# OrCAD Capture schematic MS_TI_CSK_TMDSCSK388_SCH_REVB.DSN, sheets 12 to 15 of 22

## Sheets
12 12.WLAN TRANSLATORS & CAM MUXER: size C; title: WLAN TRANSLATORS & CAM MUXER
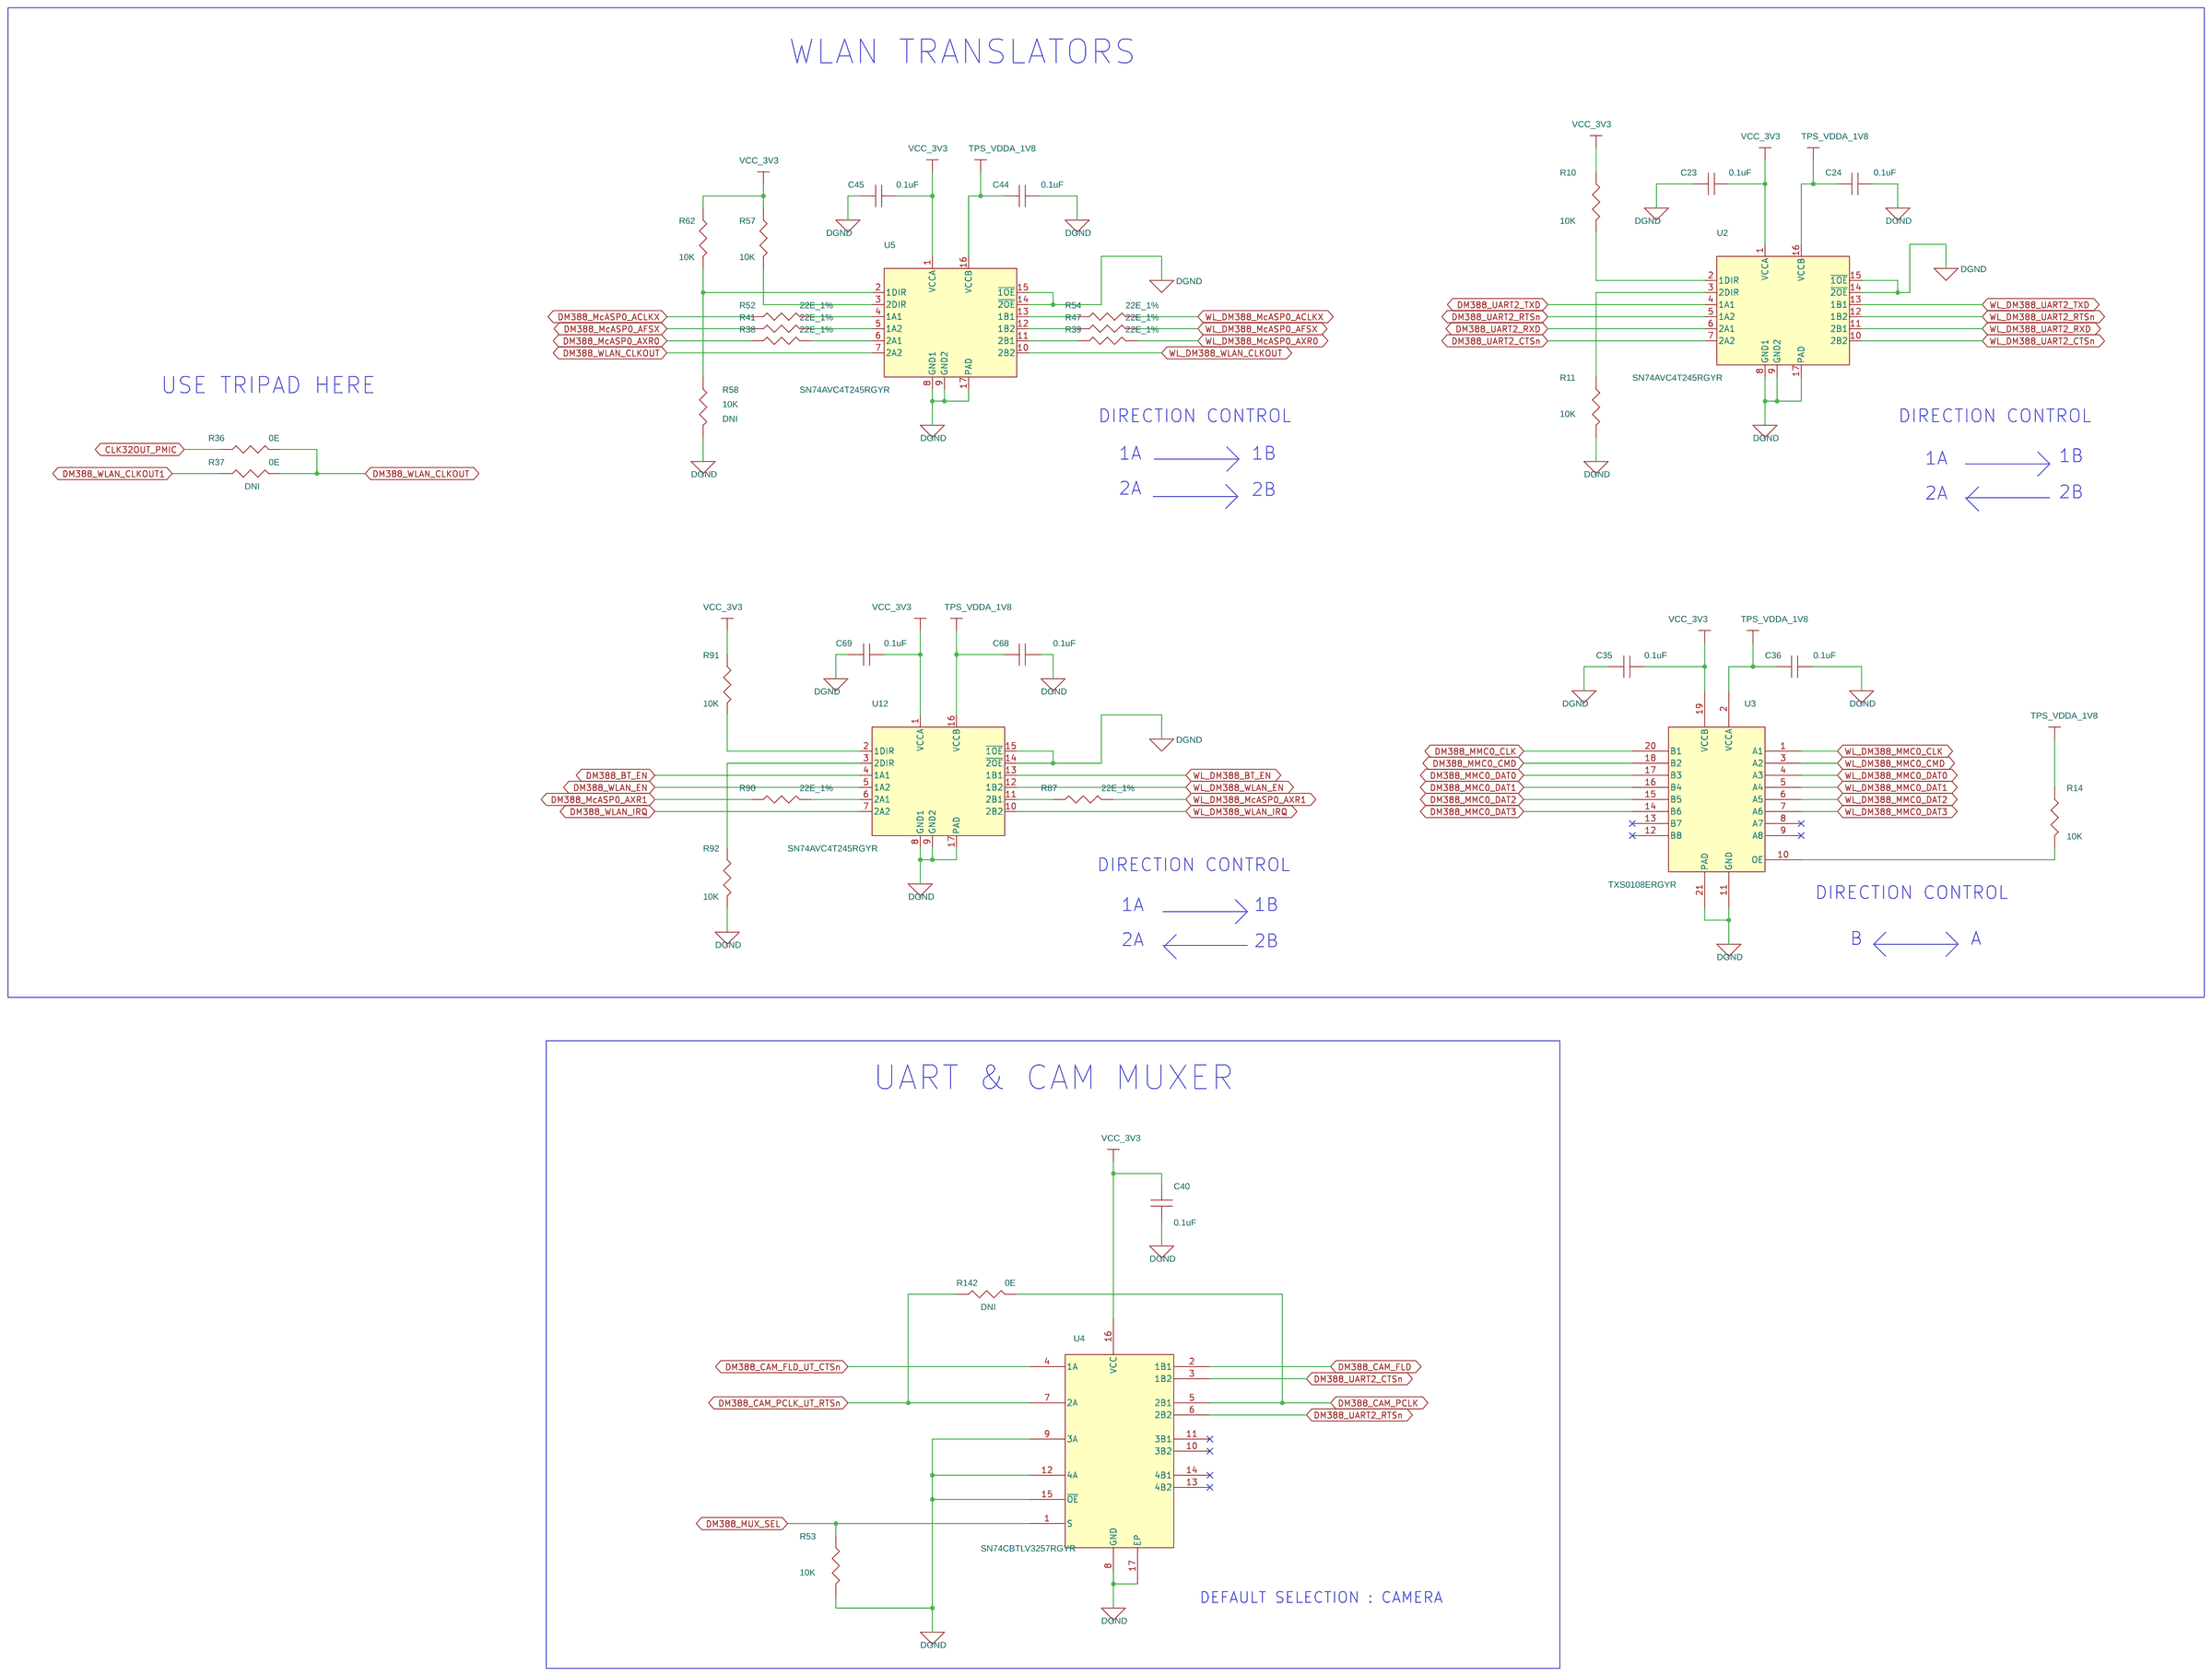
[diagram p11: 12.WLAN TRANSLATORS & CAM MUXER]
13 13.WLAN + BT MODULE: size C; title: WLAN + BT MODULE
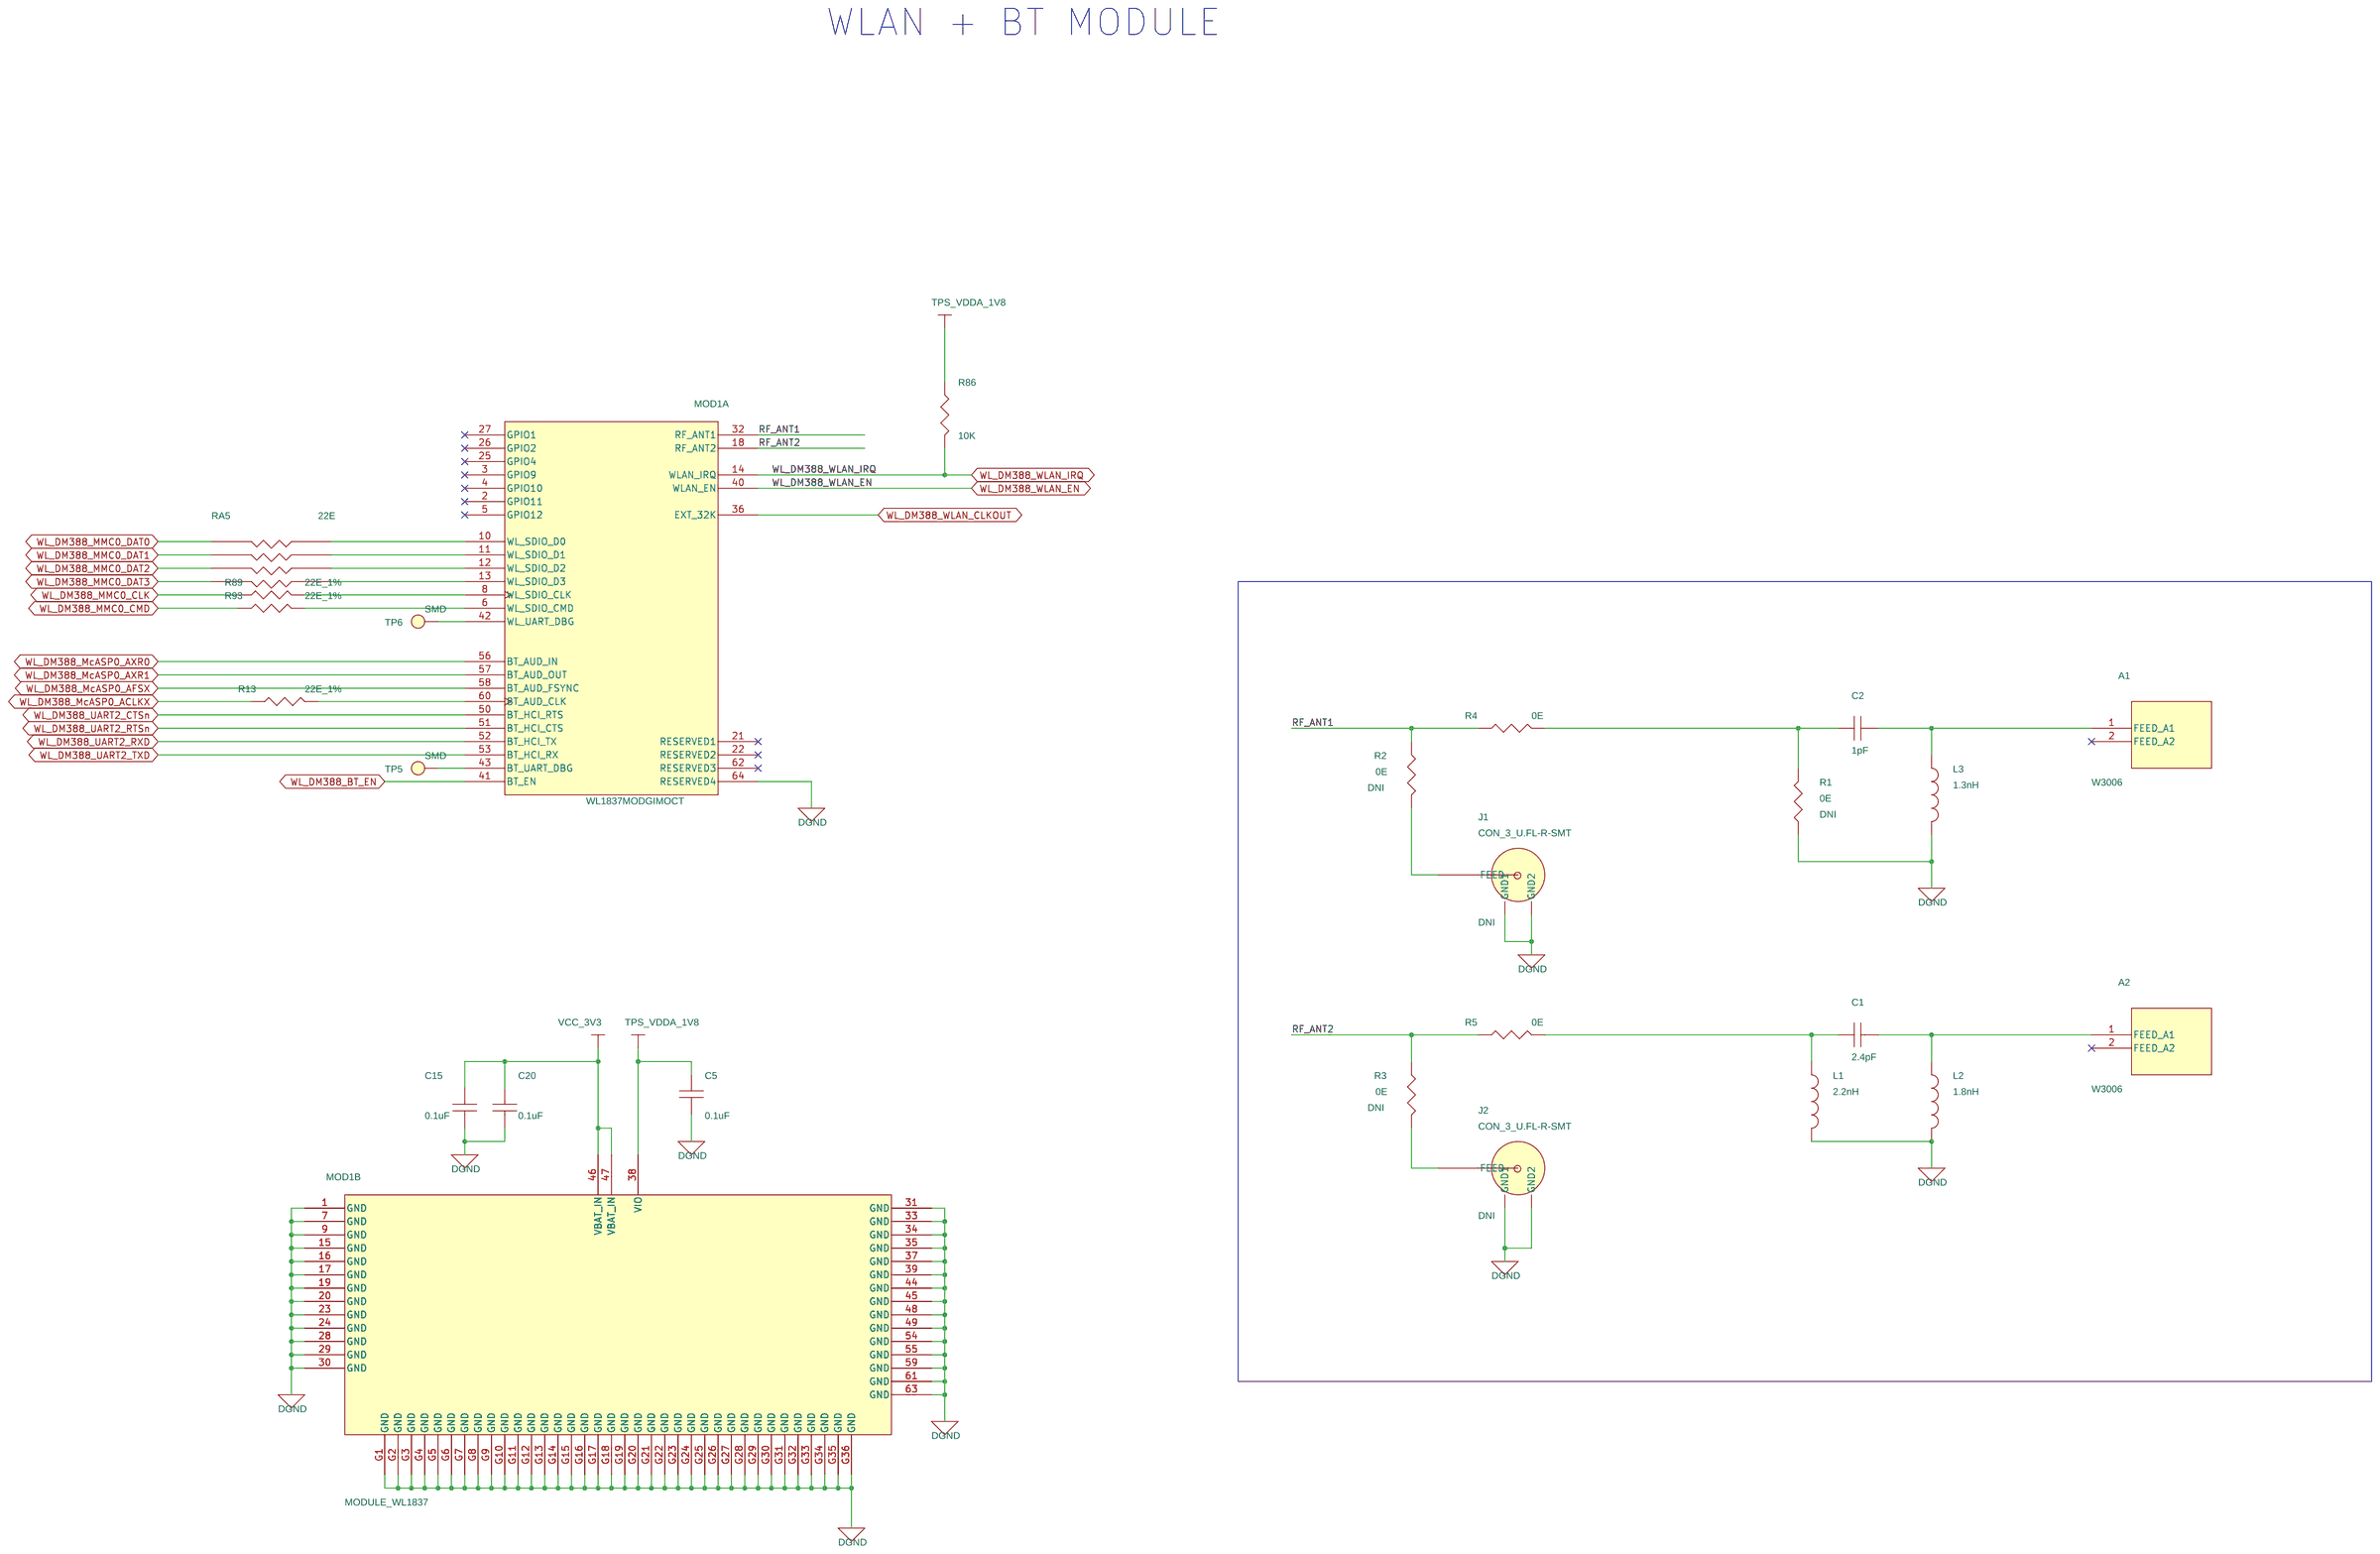
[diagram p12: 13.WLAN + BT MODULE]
14 14.DM388 POWER: size C; title: DM388 POWER
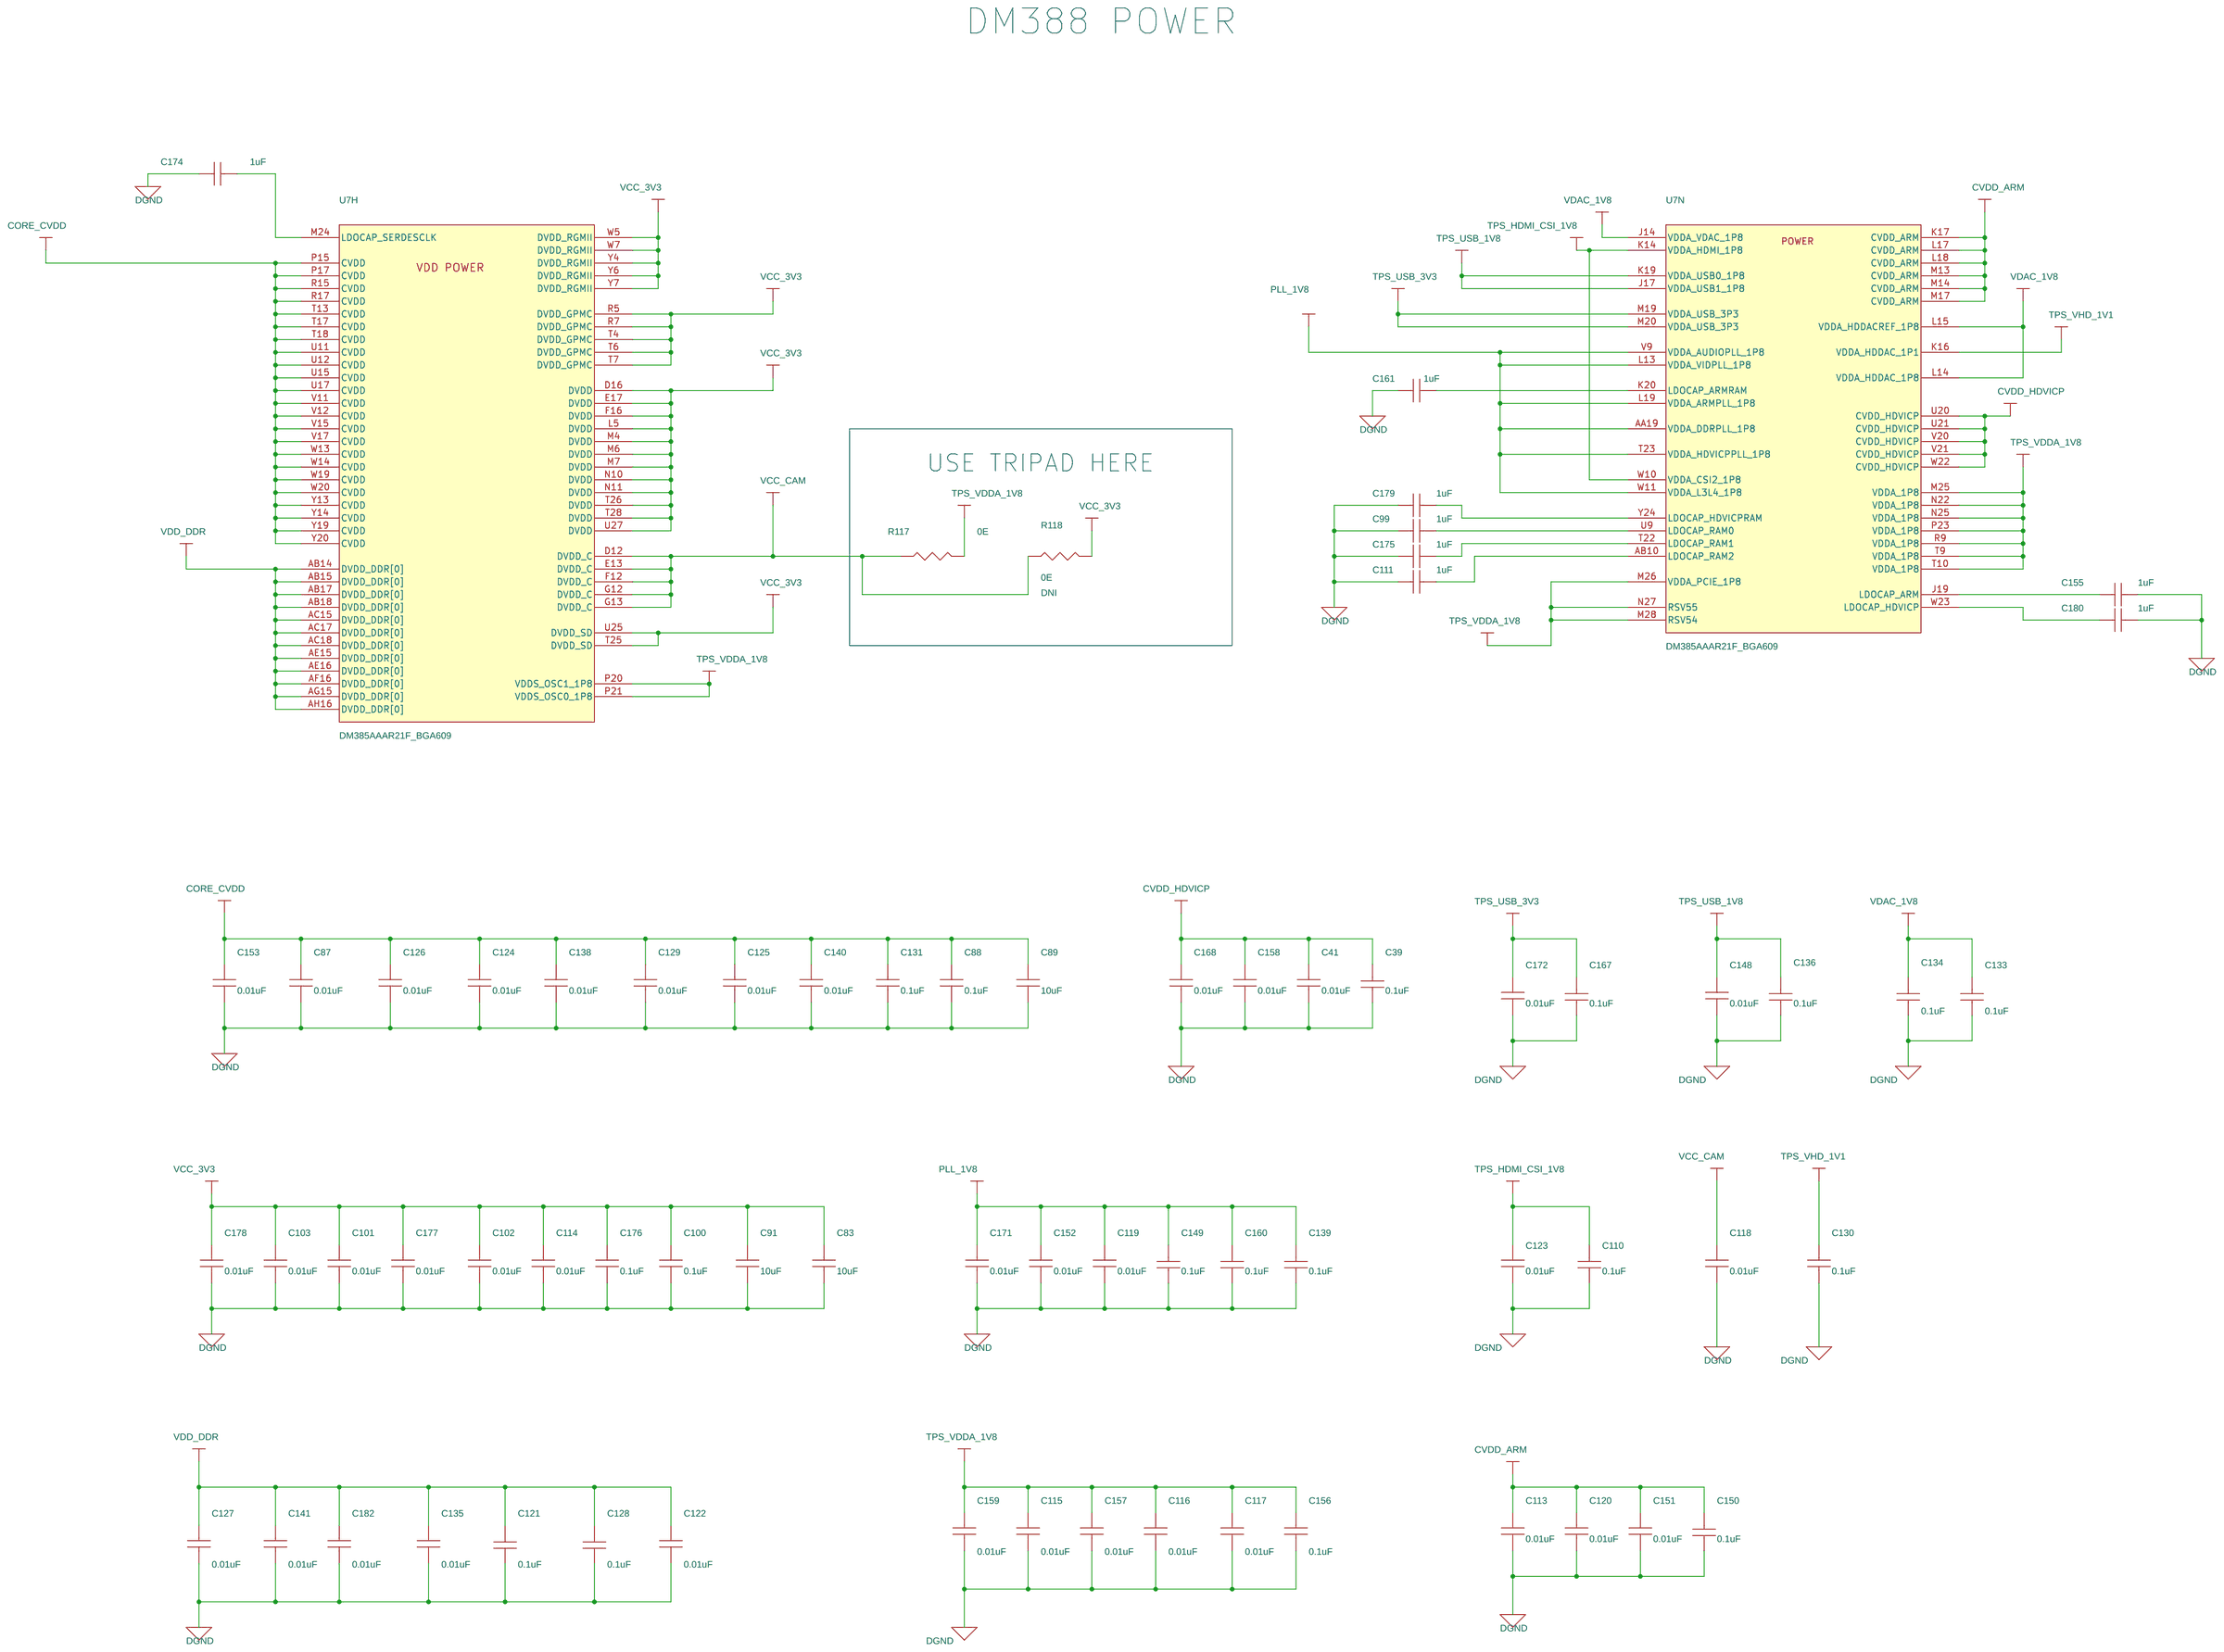
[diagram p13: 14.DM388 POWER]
15 15.DM388 VSS: size C; title: DM388 VSS
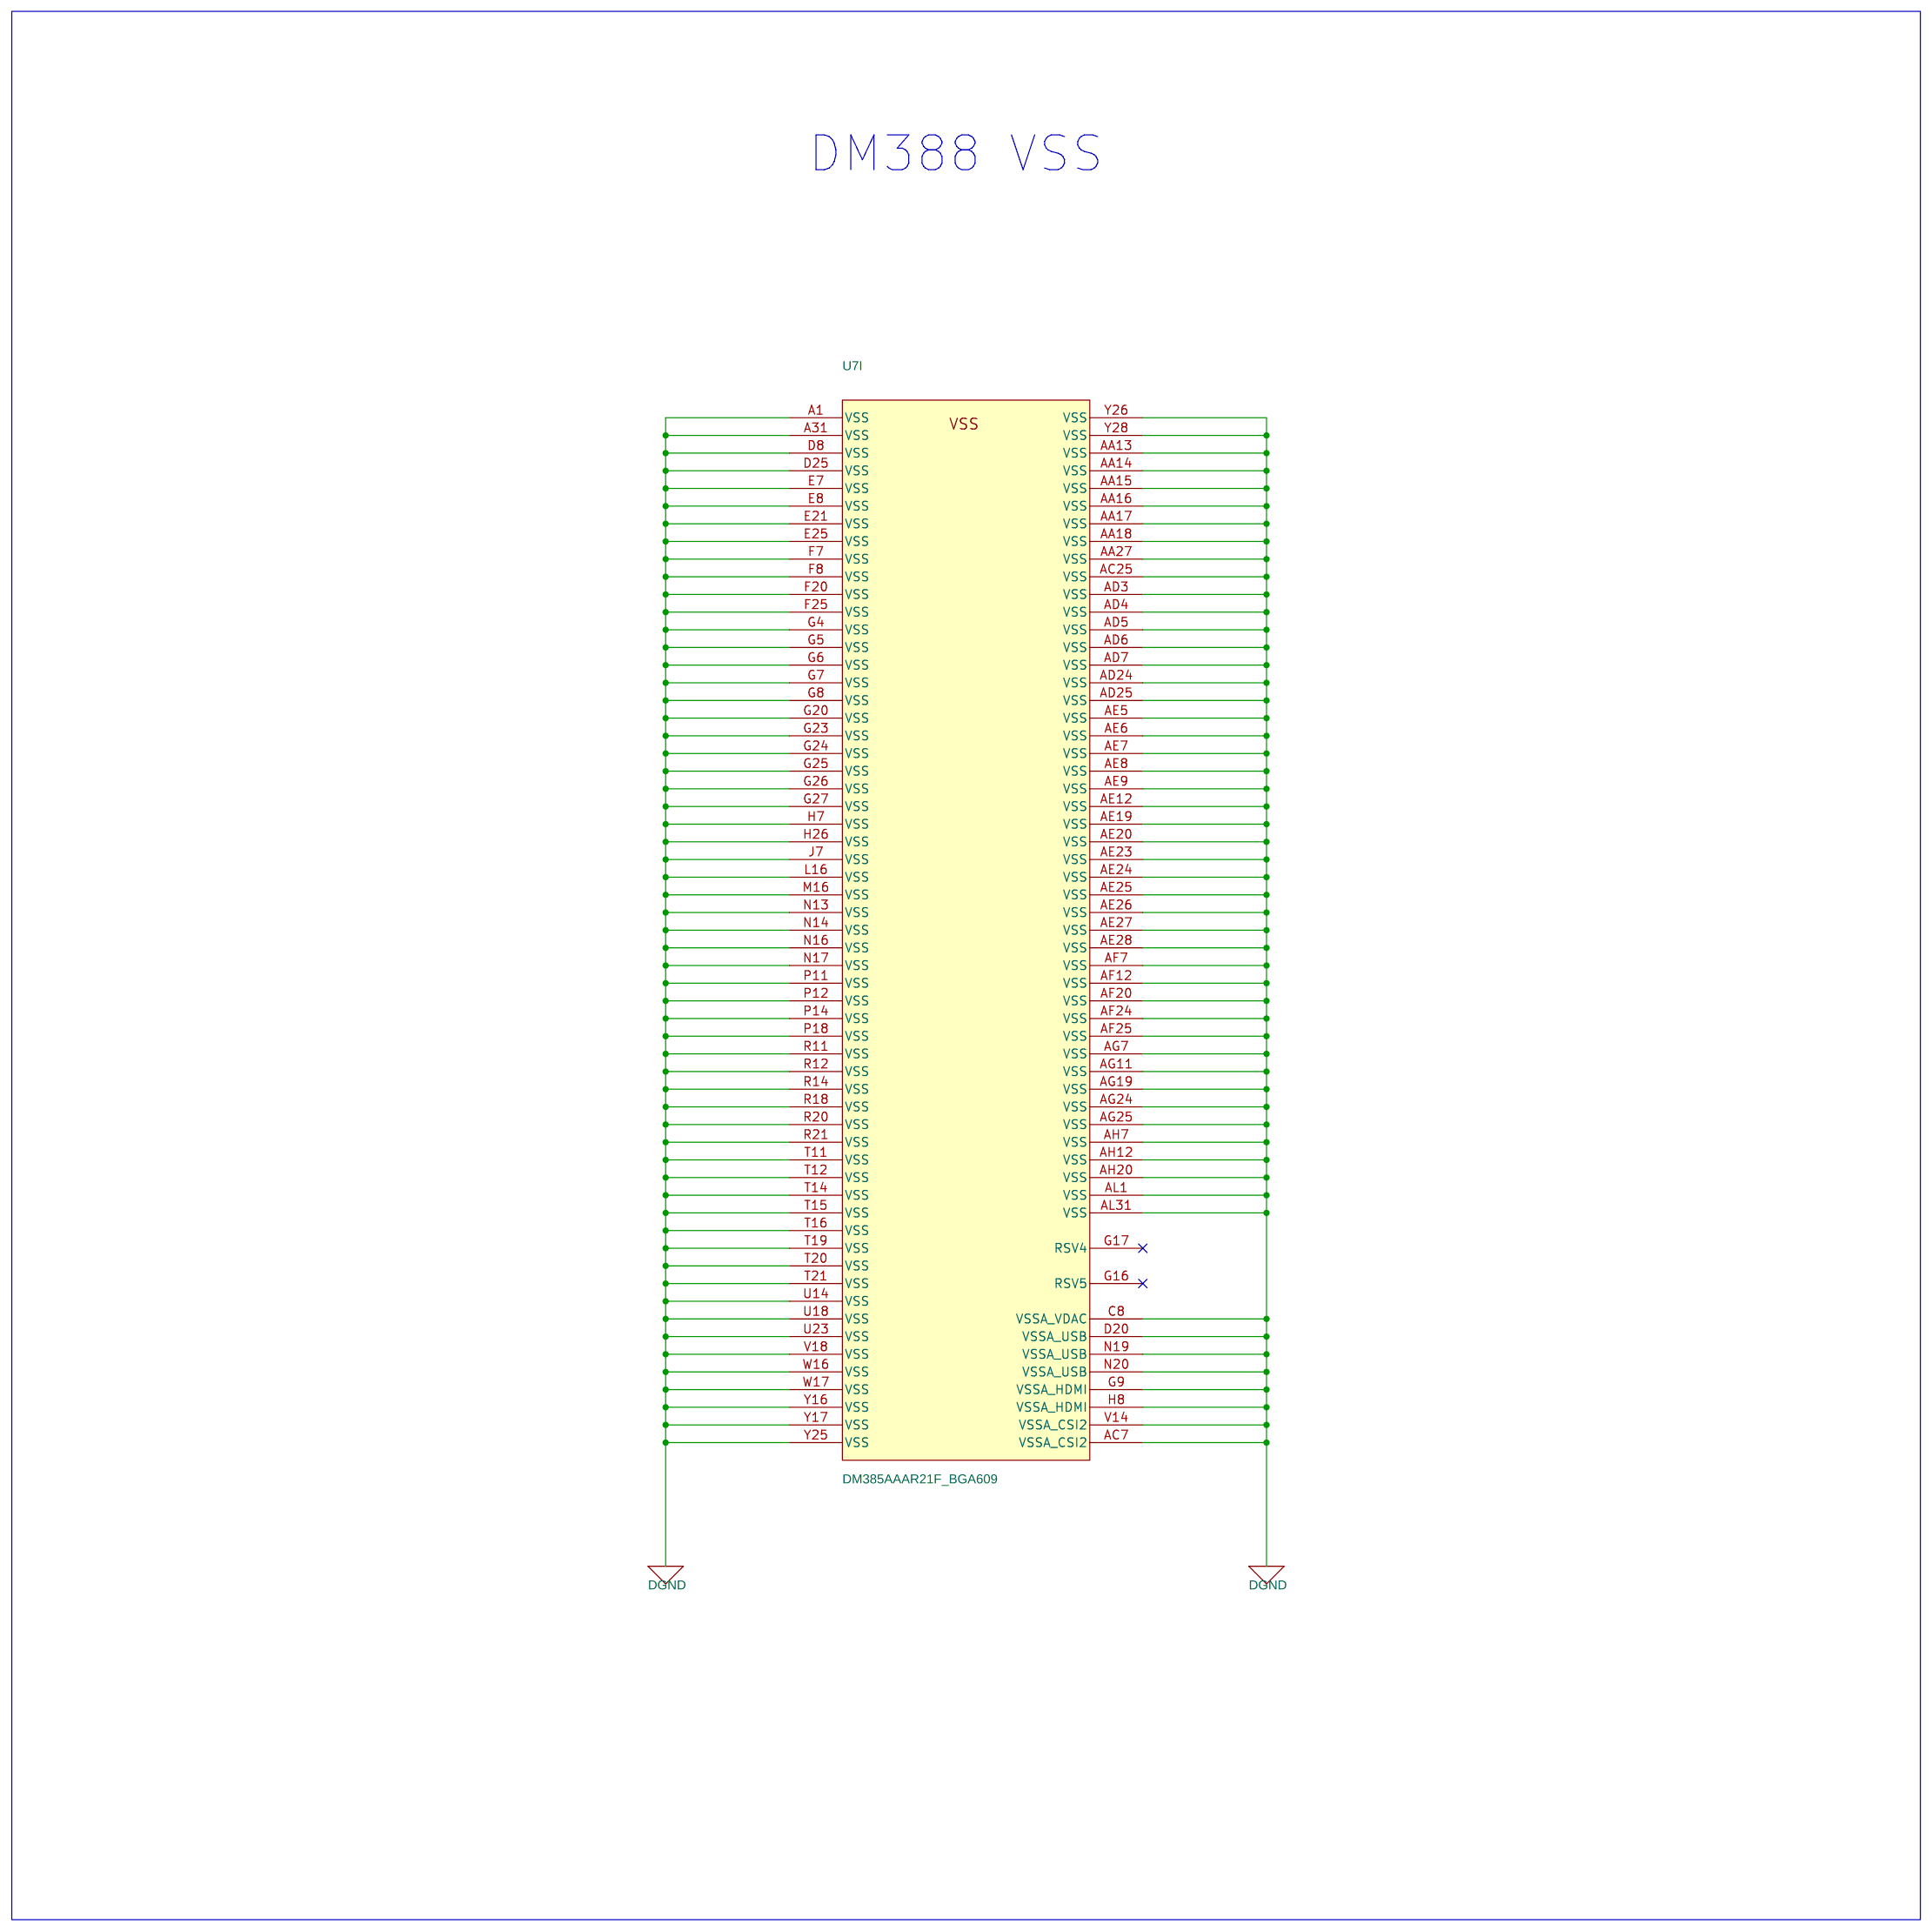
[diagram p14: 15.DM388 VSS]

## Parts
sheet 12.WLAN TRANSLATORS & CAM MUXER
C23  0.1uF  [CAP0201]
C24  0.1uF  [CAP0201]
C35  0.1uF  [CAP0201]
C36  0.1uF  [CAP0201]
C40  0.1uF  [CAP0402]
C44  0.1uF  [CAP0201]
C45  0.1uF  [CAP0201]
C68  0.1uF  [CAP0201]
C69  0.1uF  [CAP0201]
R10  10K  [RES0402]
R11  10K  [RES0402]
R14  10K  [RES0402]
R36  0E  [RES0402]
R37  0E  [RES0402]
R38  22E_1%  [RES0402]
R39  22E_1%  [RES0402]
R41  22E_1%  [RES0402]
R47  22E_1%  [RES0402]
R52  22E_1%  [RES0402]
R53  10K  [RES0402]
R54  22E_1%  [RES0402]
R57  10K  [RES0402]
R58  10K  [RES0402]
R62  10K  [RES0402]
R87  22E_1%  [RES0402]
R90  22E_1%  [RES0402]
R91  10K  [RES0402]
R92  10K  [RES0402]
R142  0E  [RES0402]
U2  SN74AVC4T245RGYR  [QFN16_19-68_160X140]
U3  TXS0108ERGYR  [QFN20_19-68_185X145]
U4  SN74CBTLV3257RGYR  [QFN16_19-68_160X140]
U5  SN74AVC4T245RGYR  [QFN16_19-68_160X140]
U12  SN74AVC4T245RGYR  [QFN16_19-68_160X140]
sheet 13.WLAN + BT MODULE
A1  W3006  [ANT2_W3006_390X130_SMD]
A2  W3006  [ANT2_W3006_390X130_SMD]
C1  2.4pF  [CAP0402]
C2  1pF  [CAP0402]
C5  0.1uF  [CAP0402]
C15  0.1uF  [CAP0402]
C20  0.1uF  [CAP0402]
J1  CON_3_U.FL-R-SMT  [CON_3X1_U-FL-R-SMT_S_S_S]
J2  CON_3_U.FL-R-SMT  [CON_3X1_U-FL-R-SMT_S_S_S]
L1  2.2nH  [IND0402]
L2  1.8nH  [IND0402]
L3  1.3nH  [IND0402]
MOD1  WL1837MODGIMOCT  [MOD100_WL1831M_530X530]  (sections A,B)
R1  0E  [RES0402]
R2  0E  [RES0402]
R3  0E  [RES0402]
R4  0E  [RES0402]
R5  0E  [RES0402]
R13  22E_1%  [RES0402]
R86  10K  [RES0402]
R89  22E_1%  [RES0402]
R93  22E_1%  [RES0402]
RA5  22E  [RESA_741X083_0402-4]
TP5  SMD  [TP40_SMD]
TP6  SMD  [TP40_SMD]
sheet 14.DM388 POWER
C39  0.1uF  [CAP0201]
C41  0.01uF  [CAP0201]
C83  10uF  [CAP0603]
C87  0.01uF  [CAP0201]
C88  0.1uF  [CAP0201]
C89  10uF  [CAP0402]
C91  10uF  [CAP0603]
C99  1uF  [CAP0402]
C100  0.1uF  [CAP0201]
C101  0.01uF  [CAP0201]
C102  0.01uF  [CAP0201]
C103  0.01uF  [CAP0201]
C110  0.1uF  [CAP0201]
C111  1uF  [CAP0402]
C113  0.01uF  [CAP0201]
C114  0.01uF  [CAP0201]
C115  0.01uF  [CAP0201]
C116  0.01uF  [CAP0201]
C117  0.01uF  [CAP0201]
C118  0.01uF  [CAP0201]
C119  0.01uF  [CAP0201]
C120  0.01uF  [CAP0201]
C121  0.1uF  [CAP0201]
C122  0.01uF  [CAP0201]
C123  0.01uF  [CAP0201]
C124  0.01uF  [CAP0201]
C125  0.01uF  [CAP0201]
C126  0.01uF  [CAP0201]
C127  0.01uF  [CAP0201]
C128  0.1uF  [CAP0201]
C129  0.01uF  [CAP0201]
C130  0.1uF  [CAP0201]
C131  0.1uF  [CAP0201]
C133  0.1uF  [CAP0201]
C134  0.1uF  [CAP0201]
C135  0.01uF  [CAP0201]
C136  0.1uF  [CAP0201]
C138  0.01uF  [CAP0201]
C139  0.1uF  [CAP0201]
C140  0.01uF  [CAP0201]
C141  0.01uF  [CAP0201]
C148  0.01uF  [CAP0201]
C149  0.1uF  [CAP0201]
C150  0.1uF  [CAP0201]
C151  0.01uF  [CAP0201]
C152  0.01uF  [CAP0201]
C153  0.01uF  [CAP0201]
C155  1uF  [CAP0402]
C156  0.1uF  [CAP0201]
C157  0.01uF  [CAP0201]
C158  0.01uF  [CAP0201]
C159  0.01uF  [CAP0201]
C160  0.1uF  [CAP0201]
C161  1uF  [CAP0402]
C167  0.1uF  [CAP0201]
C168  0.01uF  [CAP0201]
C171  0.01uF  [CAP0201]
C172  0.01uF  [CAP0201]
C174  1uF  [CAP0402]
C175  1uF  [CAP0402]
C176  0.1uF  [CAP0201]
C177  0.01uF  [CAP0201]
C178  0.01uF  [CAP0201]
C179  1uF  [CAP0402]
C180  1uF  [CAP0402]
C182  0.01uF  [CAP0201]
R117  0E  [RES0402]
R118  0E  [RES0402]
sheet 19.ETHERNET,HDMI & USB
U7  DM388AAAR21FP  [BGA609_19-68_635X635]  (sections A,B,C,D,E,F,G,H,I,J,K,L,M,N)

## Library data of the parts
C23 C24 C35 C36 C39 C44 C45 C68 C69 C88 C100 C110 C121 C128 C130 C131 C133 C134 C136 C139 C149 C150 C156 C160 C167 C176 = CAP: CAP CERAMIC 0.1uF 10V 20% X5R 0201; Chkd/date: RAGESH/290910; Crtd /date: MUDDU/290410; Custom_Duty: 15%; Customs_HS_Code: 85322990; Distributor_name: DIGIKEY; Distributor_part_number: 490-5405-1-ND; Height: 0.33MM; Mfr_name: MURATA; Mfr_part_number: GRM033R61A104ME15D; Mistral Part No: 120010040004-R; Package: 0201; Part_type: CAPACITORS\CERAMIC; Project: BUG_BASE-II; RoHS: RoHS; Temperature: -55°C+85°C; Tolerance: 20%; Voltage: 10V; Weight: NA; Datasheet: Y:\MIS_DATABASE\DATASHEETS\CAPACITORS\MURATA_CMCC.PDF
C5 C15 C20 C40 = CAP: CAP CERAMIC 0.1uF 16V 10% X7R 0402; Alternate_mfr_name_A: KEMET; Alternate_mfr_part_number_A: C0402C104K4RACT; Chkd/date: MAZHAR/281108; Crtd /date: MAZHAR/030907; Cust_part_number: 1500-80042E; Custom_Duty: 15%; Customs_HS_Code: 85322990; Distributor_name: DIGIKEY; Distributor_name_A: DIGIKEY; Distributor_part_number: 490-3261-1-ND; Distributor_part_number_A: 399-3521-1-ND; Height: 0.55MM; Mfr_name: MURATA; Mfr_part_number: GRM155R71C104KA88D; Mistral Part No: 120009030060-R; Package: 0402; Part_type: CAPACITORS\CERAMIC; Project: SMART VIEW_IP CAMERA; Tolerance: 10%; Voltage: 16V; Wattage: NA; Weight: NA; Datasheet: Y:\MIS_DATABASE\DATASHEETS\CAPACITORS\GRM188SERIES.PDF
R10 R11 R14 R53 R57 R62 R86 R91 R92 = RESISTOR: RES 10K 1/16W 5% 0402; Alternate_mfr_name_A: AVX CORPORATION; Alternate_mfr_name_B: PANASONIC-ECG-ECG; Alternate_mfr_name_C: YAGEO AMERICA; Alternate_mfr_name_D: WALSIN; Alternate_mfr_part_number_A: CR05-103J-H; Alternate_mfr_part_number_B: ERJ-2GEJ103X; Alternate_mfr_part_number_C: 9C04021A1002JLHF3; Alternate_mfr_part_number_D: WR04X103_JT; Chkd/date: SHREESHAIL/061205; Crtd /date: MAZHAR/230805; Custom_Duty: 15%; Customs_HS_Code: 85332119; Distributor_name: DIGIKEY; Distributor_name_A: MOUSER; Distributor_name_B: DIGIKEY; Distributor_name_C: DIGIKEY; Distributor_name_D: NA; Distributor_part_number: 311-10KJRCT-ND; Distributor_part_number_A: 581-CR051002JT; Distributor_part_number_B: P10KJCT-ND; Distributor_part_number_C: 311-10KJCT-ND; Distributor_part_number_D: NA; Height: 0.40MM; Mfr_name: YAGEO AMERICA; Mfr_part_number: RC0402JR-0710KL; Mistral Part No: 110009030208-P; Package: 0402; Part_type: RESISTORS\FIXED; Project: HSE; RoHS: Pb-Free; Tolerance: 5%; Wattage: 1/16W; Datasheet: Y:\MIS_DATABASE\DATASHEETS\RESISTORS\YAGEO-RC0402.PDF
R4 R5 R36 = RESISTOR: RES 0E 1/16W 5% 0402; Chkd/date: USMAN240712; Crtd /date: CHAITHANYA/300911; Custom_Duty: 15%; Customs_HS_Code: 85332119; Distributor_name: DIGIKEY; Distributor_part_number: 311-0.0JRCT-ND; Height: 0.40MM; Mfr_name: YAGEO; Mfr_part_number: RC0402JR-070RL; Mistral Part No: 110011090036-R; Package: 0402; Part_type: RESISTORS\FIXED; Project: VP-4000-PROCESSOR; RoHS: RoHS; SIGNAL_MODEL: RESISTOR_RES0402_0E_0E; Temperature: -55°C+155°C; Tolerance: 5%; Voltage: NA; Wattage: 1/16W; Weight: NA; Datasheet: Y:\MIS_DATABASE\DATASHEETS\RESISTORS\YAGEO_RC0402JR.PDF
R1-R3 R37 R142 = RESISTOR: RES 0E 1/16W 5% 0402; Chkd/date: USMAN240712; Crtd /date: CHAITHANYA/300911; Custom_Duty: 15%; Customs_HS_Code: 85332119; Distributor_name: DIGIKEY; Distributor_part_number: 311-0.0JRCT-ND; Height: 0.40MM; Loading: DNI; Mfr_name: YAGEO; Mfr_part_number: RC0402JR-070RL; Mistral Part No: 110011090036-R; Package: 0402; Part_type: RESISTORS\FIXED; Project: VP-4000-PROCESSOR; RoHS: RoHS; SIGNAL_MODEL: RESISTOR_RES0402_0E_0E; Temperature: -55°C+155°C; Tolerance: 5%; Voltage: NA; Wattage: 1/16W; Weight: NA; Datasheet: Y:\MIS_DATABASE\DATASHEETS\RESISTORS\YAGEO_RC0402JR.PDF
R13 R38 R39 R41 R47 R52 R54 R87 R89 R90 R93 = RESISTOR: RES 22E 1/16W 1% 0402; Alternate_mfr_name_A: VISHAY; Alternate_mfr_part_number_A: CRCW040222R0FKED; Chkd/date: SUHAS/290910; Crtd /date: MAZHAR/090909; Cust_part_number: 4700-80047E; Custom_Duty: 15%; Customs_HS_Code: 85332119; Distributor_name: DIGIKEY; Distributor_name_A: DIGIKEY; Distributor_part_number: 311-22.0LRCT-ND; Distributor_part_number_A: 541-22.0LCT-ND; Height: 0.40MM; Mfr_name: YAGEO AMERICA; Mfr_part_number: RC0402FR-0722RL; Mistral Part No: 110009090004-P; Package: 0402; Part_type: RESISTORS\FIXED; Project: VMEFMCD; Remarks: In alternate datasheet it is RoHS COMPLIANT. Y:\MIS_DATABASE\DATASHEETS\RESISTORS\CRCW0402.PDF; RoHS: Pb-Free; Temperature: -55°C+155°C; Tolerance: 1%; Voltage: 50V; Wattage: 1/16W; Weight: 0.8g/1000pcs; Datasheet: Y:\MIS_DATABASE\DATASHEETS\RESISTORS\YAGEO-RC0402.PDF
R58 = RESISTOR: RES 10K 1/16W 5% 0402; Alternate_mfr_name_A: AVX CORPORATION; Alternate_mfr_name_B: PANASONIC-ECG-ECG; Alternate_mfr_name_C: YAGEO AMERICA; Alternate_mfr_name_D: WALSIN; Alternate_mfr_part_number_A: CR05-103J-H; Alternate_mfr_part_number_B: ERJ-2GEJ103X; Alternate_mfr_part_number_C: 9C04021A1002JLHF3; Alternate_mfr_part_number_D: WR04X103_JT; Chkd/date: SHREESHAIL/061205; Crtd /date: MAZHAR/230805; Custom_Duty: 15%; Customs_HS_Code: 85332119; Distributor_name: DIGIKEY; Distributor_name_A: MOUSER; Distributor_name_B: DIGIKEY; Distributor_name_C: DIGIKEY; Distributor_name_D: NA; Distributor_part_number: 311-10KJRCT-ND; Distributor_part_number_A: 581-CR051002JT; Distributor_part_number_B: P10KJCT-ND; Distributor_part_number_C: 311-10KJCT-ND; Distributor_part_number_D: NA; Height: 0.40MM; Loading: DNI; Mfr_name: YAGEO AMERICA; Mfr_part_number: RC0402JR-0710KL; Mistral Part No: 110009030208-P; Package: 0402; Part_type: RESISTORS\FIXED; Project: HSE; RoHS: Pb-Free; Tolerance: 5%; Wattage: 1/16W; Datasheet: Y:\MIS_DATABASE\DATASHEETS\RESISTORS\YAGEO-RC0402.PDF
U2 U5 U12 = SN74AVC4T245RGYR_QFN16: IC 4-BIT DUAL SUPPLY BUS TRANSCEIVER QFN16; Chkd/date: MAZHAR/060308; Crtd /date: USMAN/060308; Custom_Duty: 15%; Customs_HS_Code: 85423100; Distributor_name: DIGIKEY; Distributor_part_number: 296-18231-1-ND; Height: 1.00MM; Mfr_name: TEXAS INSTRUMENTS; Mistral Part No: 141009030112-R; Package: QFN16; Part_type: ICS\DIGITAL\COMBINATIONAL; Project: HS100RD; RoHS: Sb/ Br FREE; Datasheet: Y:\MIS_DATABASE\DATASHEETS\ICS\DIGITAL\BUSTRANSCEIVER\SN74AVC4T245XXXX.PDF
U3 = TXS0108ERGYR_QFN20: IC TRANSLATOR BIDIRECTIONAL VOLTAGE-LEVEL 8BIT QFN20; Chkd/date: RAVI/050311; Crtd /date: BAVISH/280411; Custom_Duty: 15%; Customs_HS_Code: 85423100; Distributor_name: DIGIKEY; Distributor_part_number: 296-24806-1-ND; Height: 1.00MM; Mfr_name: TEXAS INSTRUMENTS; Mistral Part No: 141011040019-R; Package: QFN20; Part_type: ICS\INTERFACE; Project: OMAPL1_PEC20; RoHS: RoHS; Temperature: -40°C+85°C; Tolerance: NA; Voltage: NA; Wattage: NA; Weight: NA; Datasheet: Y:\MIS_DATABASE\DATASHEETS\ICS\INTERFACE\TXS0108E.PDF
U4 = SN74CBTLV3257RGYR_QFN16: IC 1OF 2 FET MULTIPLEXER/DEMULTIPLEXER QFN16; Chkd/date: VASANTHA/250516; Crtd /date: VASANTHA/250516; Custom_Duty: 15%; Customs_HS_Code: 85423100; Distributor_name: DIGIKEY; Distributor_part_number: 296-15107-1-ND; Height: 1.00MM; Mfr_name: TEXAS INSTRUMENTS; Mistral Part No: 141016050009-R; Package: QFN16; Part_type: ICS\DIGITAL\COMBINATIONAL; Project: TMDXCSK388; RoHS: RoHS; Temperature: -40°C+85°C; Tolerance: NA; Voltage: NA; Wattage: NA; Weight: NA; Datasheet: Y:\MIS_DATABASE\DATASHEETS\ICS\DIGITAL\COMBINATIONAL\SN74CBTLV3257.PDF
A1 A2 = ANT_431115300245: ANTENNA  DUALBAND W-LAN CERAMIC CHIP SMD; Chkd/date: NAVEED/280115; Crtd /date: VASANTHA/080115; Distributor_name: MOUSER; Distributor_part_number: 673-W3006; Height: 1.50MM; Mfr_name: MAXIM; Mistral Part No: 130015010025-R; Package: SMD; Part_type: MISC\ANTENNA; Project: DCMIST_WLAN; RoHS: RoHS; Temperature: -40°C+85°C; Tolerance: NA; Voltage: NA; Wattage: NA; Weight: 240mg; Datasheet: Y:\MIS_DATABASE\DATASHEETS\ANTENNAS\W3006.PDF
C1 = CAP: CAP CERAMIC 2.4pF 50V 0.1pF C0G 0402; Chkd/date: VASANTHA/300516; Crtd /date: VASANTHA/300516; Custom_Duty: 15%; Customs_HS_Code: 85322990; Distributor_name: DIGIKEY; Distributor_part_number: 490-8093-1-ND; Height: 0.55MM; Mfr_name: MURATA; Mfr_part_number: GJM1555C1H2R4BB01D; Mistral Part No: 120016050011-R; Package: 0402; Part_type: CAPACITORS\CERAMIC; Project: TMDXCSK368; RoHS: RoHS; Temperature: -55°C+125°C; Tolerance: 0.1pF; Voltage: 50V; Wattage: NA; Weight: NA; Datasheet: Y:\MIS_DATABASE\DATASHEETS\CAPACITORS\GRM188SERIES.PDF
C2 = CAP: CAP CERAMIC 1pF 50V 0.1pF C0G 0402; Chkd/date: VASANTHA/300516; Crtd /date: VASANTHA/300516; Custom_Duty: 15%; Customs_HS_Code: 85322990; Distributor_name: DIGIKEY; Distributor_part_number: 490-6073-1-ND; Height: 0.55MM; Mfr_name: MURATA; Mfr_part_number: GJM1555C1H1R0BB01D; Mistral Part No: 120016050010-R; Package: 0402; Part_type: CAPACITORS\CERAMIC; Project: TMDXCSK368; RoHS: RoHS; Temperature: -55°C+125°C; Tolerance: 0.1pF; Voltage: 50V; Wattage: NA; Weight: NA; Datasheet: Y:\MIS_DATABASE\DATASHEETS\CAPACITORS\GRM188SERIES.PDF
J1 J2 = CON_3_U.FL-R-SMT: CON MICRO COAXIAL FEMALE SMD; Chkd/date: NAVEED/301214; Crtd /date: USMAN/230309; Custom_Duty: 24%; Customs_HS_Code: 85369090; Distributor_name: DIGIKEY; Distributor_part_number: H9161-ND; Height: 1.25MM; Loading: DNI; Mfr_name: HIROSE ELECTRIC EUROPE; Mfr_part_number: U.FL-R-SMT-1(01); Mistral Part No: 150009030465-R; Package: SMD; Part_type: CONNECTOR\MISCELLANEOUS; Project: AXON; RoHS: RoHS; Tolerance: NA; Voltage: NA; Wattage: NA; Datasheet: Y:\MIS_DATABASE\DATASHEETS\CONNECTORS\U.FL-R-SMT.PDF
L1 = INDUCTOR: IND CHIP COIL 2.2nH 220mA 0.1nH 0402; Chkd/date: VASANTHA/300516; Crtd /date: VASANTHA/300516; Custom_Duty: 24%; Customs_HS_Code: 85437099; Distributor_name: DIGIKEY; Distributor_part_number: 490-1128-1-ND; Height: 0.45MM; Mfr_name: MURATA; Mfr_part_number: LQP15MN2N2B02D; Mistral Part No: 130016050046-R; Package: 0402; Project: TMDXCSK368; RoHS: RoHS; Temperature: -40°C+85°C; Tolerance: 0.1nH; Voltage: NA; Wattage: NA; Weight: NA; Datasheet: Y:\MIS_DATABASE\DATASHEETS\DISCRETES\INDUCTORS\LQP15M.PDF
L2 = INDUCTOR: IND CHIP COIL 1.8nH 280mA 0.1nH 0402; Chkd/date: VASANTHA/300516; Crtd /date: VASANTHA/300516; Custom_Duty: 24%; Customs_HS_Code: 85437099; Distributor_name: DIGIKEY; Distributor_part_number: 490-1127-1-ND; Height: 0.45MM; Mfr_name: MURATA; Mfr_part_number: LQP15MN1N8B02D; Mistral Part No: 130016050045-R; Package: 0402; Project: TMDXCSK368; RoHS: RoHS; Temperature: -40°C+85°C; Tolerance: 0.1nH; Voltage: NA; Wattage: NA; Weight: NA; Datasheet: Y:\MIS_DATABASE\DATASHEETS\DISCRETES\INDUCTORS\LQP15M.PDF
L3 = INDUCTOR: IND CHIP COIL 1.3nH 280mA 0.1nH 0402; Chkd/date: VASANTHA/300516; Crtd /date: VASANTHA/300516; Custom_Duty: 24%; Customs_HS_Code: 85437099; Distributor_name: DIGIKEY; Distributor_part_number: 490-6748-1-ND; Height: 0.45MM; Mfr_name: MURATA; Mfr_part_number: LQP15MN1N3B02D; Mistral Part No: 130016050044-R; Package: 0402; Project: TMDXCSK368; RoHS: RoHS; Temperature: -40°C+85°C; Tolerance: 0.1nH; Voltage: NA; Wattage: NA; Weight: NA; Datasheet: Y:\MIS_DATABASE\DATASHEETS\DISCRETES\INDUCTORS\LQP15M.PDF
MOD1 = MODULE_WL1837: MODULE WIFI WILINK BLUETOOTH SMD100; Chkd/date: VASANTHA/130516; Crtd /date: VASANTHA/130516; Distributor_name: DIGIKEY; Distributor_part_number: 296-43667-1-ND; Height: 2.00MM; Mfr_name: TEXAS INSTRUMENTS; Mistral Part No: 180016050002-R; Package: SMD100; Part_type: MISC\IOMODULE; Project: TMDXCSK8127; RoHS: RoHS; Temperature: -40°C+85°C; Tolerance: NA; Voltage: NA; Wattage: NA; Weight: NA; Color: Default; Location X-Coordinate: 0; Location Y-Coordinate: 0; Power Pins Visible: False; Primitive: DEFAULT; Datasheet: Y:\MIS_DATABASE\DATASHEETS\MISC\MODULES\WL1837XXXPDF
RA5 = RESARR_ISO4: RES ARRAY 4RES 22E 62.5mW 5% 0402; Chkd/date: VASANTHA/130516; Crtd /date: VASANTHA/130516; Distributor_name: DIGIKEY; Distributor_part_number: 741X083220JPCT-ND; Height: 0.50MM; Mfr_name: CTS; Mfr_part_number: 741X083220JP; Mistral Part No: 110016050004-R; Package: 0402; Part_type: RESISTORS\ARRAY; Project: TMDXCSK368; RoHS: RoHS; Temperature: -55°C+125°C; Tolerance: 5%; Voltage: NA; Wattage: 62.5mW; Weight: NA; Datasheet: Y:\MIS_DATABASE\DATASHEETS\RESISTORS\741C083.PDF
TP5 TP6 = TESTPOINT: TESTPOINT 40 SMD; Chkd/date: MAZHAR/190505; Crtd /date: MAZHAR/190505; Distributor_name: NA; Distributor_part_number: NA; Height: NA; Mfr_name: LOCAL; Mistral Part No: 130009030933; Part_type: MISC\TESTPOINT; Project: RAINIER-3
C41 C87 C101-C103 C113-C120 C122-C127 C129 C135 C138 C140 C141 C148 C151-C153 C157-C159 C168 C171 C172 C177 C178 C182 = CAP: CAP CERAMIC 0.01uF 10V 10% X7R 0201; Chkd/date: MAZHAR/301208; Crtd /date: MAZHAR/080306; Cust_part_number: 1500-80097E; Custom_Duty: 15%; Customs_HS_Code: 85322990; Distributor_name: DIGIKEY; Distributor_part_number: 490-3194-1-ND; Height: 0.33MM; Mfr_name: MURATA; Mfr_part_number: GRM033R71A103KA01D; Mistral Part No: 120009030029-R; Package: 0201; Part_type: CAPACITORS\CERAMIC; Project: J32; RoHS: RoHS; Tolerance: 10%; Voltage: 10V; Datasheet: Y:\MIS_DATABASE\DATASHEETS\CAPACITORS\GRM033.PDF
C83 C91 = CAP: CAP CERAMIC 10uF 10V 10% X5R 0603; Chkd/date: RAGESH/280910; Crtd /date: MUDDU/040810; Custom_Duty: 15%; Customs_HS_Code: 85322990; Distributor_name: NA; Distributor_part_number: NA; Height: 0.90MM; Mfr_name: SAMSUNG; Mfr_part_number: CL10A106KP8NNNC; Mistral Part No: 120010080001; Package: 0603; Part_type: CAPACITORS\CERAMIC; Project: PB_BUGBASE; Temperature: -55°C+85°C; Tolerance: 10%; Voltage: 10V; Weight: NA; Datasheet: Y:\MIS_DATABASE\DATASHEETS\CAPACITORS\SAM-CL.PDF
C89 = CAP: CAP CERAMIC 10uF 6.3V 20% X5R 0402; Chkd/date: VASANTHA/120516; Crtd /date: VASANTHA/120516; Custom_Duty: 15%; Customs_HS_Code: 85322990; Distributor_name: DIGIKEY; Distributor_part_number: 1276-1451-1-ND; Height: 0.55MM; Mfr_name: SAMSUNG ELECTRO MECHANIC; Mfr_part_number: CL05A106MQ5NUNC; Mistral Part No: 120014120008-R; Package: 0402; Part_type: CAPACITORS\CERAMIC; Project: TMDXCSK368; RoHS: RoHS; Temperature: -55°C+85°C; Tolerance: 20%; Voltage: 6.3V; Wattage: NA; Weight: NA; Datasheet: Y:\MIS_DATABASE\DATASHEETS\CAPACITORS\CL_SERIES.PDF
C99 C111 C155 C161 C174 C175 C179 C180 = CAP: CAP CERAMIC 1uF 10V 10% X5R 0402; Chkd/date: SHREESHAIL/290507; Crtd /date: MAZHAR/290806; Custom_Duty: 15%; Customs_HS_Code: 85322990; Distributor_name: DIGIKEY; Distributor_part_number: 490-3890-1-ND; Height: 0.55MM; Mfr_name: MURATA; Mfr_part_number: GRM155R61A105KE15D; Mistral Part No: 120009030264; Package: 0402; Part_type: CAPACITORS\CERAMIC; Project: SVDO_RMB_MMA; Tolerance: 10%; Voltage: 10V; Datasheet: Y:\MIS_DATABASE\DATASHEETS\CAPACITORS\GRM188SERIES.PDF
R117 = R: RES 0E 1/10W 5% 0402; Chkd/date: NAVEED/241114; Crtd /date: NAVEED/201014; Custom_Duty: 15%; Customs_HS_Code: 85332119; Distributor_name: DIGIKEY; Distributor_part_number: P0.0JCT-ND; Height: 0.40MM; Mfr_name: PANASONIC-ECG; Mfr_part_number: ERJ-2GE0R00X; Mistral Part No: 110014100008-R; Package: 0402; Part_type: RESISTORS\FIXED; Project: AEGIS POM; RoHS: RoHS; Tolerance: 5%; Wattage: 1/10W; Datasheet: Y:\MIS_DATABASE\DATASHEETS\RESISTORS\ERJ12.PDF
R118 = R: RES 0E 1/10W 5% 0402; Chkd/date: NAVEED/241114; Crtd /date: NAVEED/201014; Custom_Duty: 15%; Customs_HS_Code: 85332119; Distributor_name: DIGIKEY; Distributor_part_number: P0.0JCT-ND; Height: 0.40MM; Loading: DNI; Mfr_name: PANASONIC-ECG; Mfr_part_number: ERJ-2GE0R00X; Mistral Part No: 110014100008-R; Package: 0402; Part_type: RESISTORS\FIXED; Project: AEGIS POM; RoHS: RoHS; Tolerance: 5%; Wattage: 1/10W; Datasheet: Y:\MIS_DATABASE\DATASHEETS\RESISTORS\ERJ12.PDF
U7 = DM385AAAR21F_BGA609: IC PROCESSOR DIGITAL MEDIA FCBGA609; Chkd/date: VASANTHA/170516; Color: Default; Crtd /date: VASANTHA/170516; Custom_Duty: 15%; Customs_HS_Code: 85423100; Distributor_name: NA; Distributor_part_number: NA; Height: 1.32MM; Location X-Coordinate: 0; Location Y-Coordinate: 0; Mfr_name: TEXAS INSTRUMENTS; Mistral Part No: 141216050002-R; Package: FCBGA609; Part_type: ICS\DIGITAL\MICROPROCESSOR; Power Pins Visible: False; Primitive: DEFAULT; Project: TMDXCSK388; RoHS: RoHS; Temperature: 0°C+95°C; Tolerance: NA; Voltage: NA; Wattage: NA; Weight: NA; Datasheet: Y:\MIS_DATABASE\DATASHEETS\ICS\DIGITAL\MICROCONTROLLER\DM385-88.PDF

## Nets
DGND: C5.2 C15.2 C20.2 C23.2 C24.2 C35.2 C36.2 C39.1 C40.2 C41.2 C44.2 C45.2 C68.2 C69.2 C83.2 C87.2 C88.2 C89.2 C91.2 C99.1 C100.2 C101.2 C102.2 C103.2 C110.1 C111.1 C113.2 C114.2 C115.2 C116.2 C117.2 C118.2 C119.2 C120.2 C121.1 C122.2 C123.2 C124.2 C125.2 C126.2 C127.2 C128.1 C129.2 C130.2 C131.2 C133.1 C134.1 C135.2 C136.1 C138.2 C139.1 C140.2 C141.2 C148.2 C149.1 C150.1 C151.2 C152.2 C153.2 C155.2 C156.2 C157.2 C158.2 C159.2 C160.1 C161.1 C167.1 C168.2 C171.2 C172.2 C174.1 C175.1 C176.2 C177.2 C178.2 C179.1 C180.2 C182.2 J1.2(GND1) J1.3(GND2) J2.2(GND1) J2.3(GND2) L1.2 L2.2 L3.2 MOD1.1(GND) MOD1.7(GND) MOD1.9(GND) MOD1.15(GND) MOD1.16(GND) MOD1.17(GND) MOD1.19(GND) MOD1.20(GND) MOD1.23(GND) MOD1.24(GND) MOD1.28(GND) MOD1.29(GND) MOD1.30(GND) MOD1.31(GND) MOD1.33(GND) MOD1.34(GND) MOD1.35(GND) MOD1.37(GND) MOD1.39(GND) MOD1.44(GND) MOD1.45(GND) MOD1.48(GND) MOD1.49(GND) MOD1.54(GND) MOD1.55(GND) MOD1.59(GND) MOD1.61(GND) MOD1.63(GND) MOD1.64(RESERVED4) MOD1.G1(GND) MOD1.G2(GND) MOD1.G3(GND) MOD1.G4(GND) MOD1.G5(GND) MOD1.G6(GND) MOD1.G7(GND) MOD1.G8(GND) MOD1.G9(GND) MOD1.G10(GND) MOD1.G11(GND) MOD1.G12(GND) MOD1.G13(GND) MOD1.G14(GND) MOD1.G15(GND) MOD1.G16(GND) MOD1.G17(GND) MOD1.G18(GND) MOD1.G19(GND) MOD1.G20(GND) MOD1.G21(GND) MOD1.G22(GND) MOD1.G23(GND) MOD1.G24(GND) MOD1.G25(GND) MOD1.G26(GND) MOD1.G27(GND) MOD1.G28(GND) MOD1.G29(GND) MOD1.G30(GND) MOD1.G31(GND) MOD1.G32(GND) MOD1.G33(GND) MOD1.G34(GND) MOD1.G35(GND) MOD1.G36(GND) R1.1 R11.2 R53.2 R58.2 R92.2 U2.8(GND1) U2.9(GND2) U2.14(~{2OE}) U2.15(~{1OE}) U2.17(PAD) U3.11(GND) U3.21(PAD) U4.8(GND) U4.9(3A) U4.12(4A) U4.15(~{OE}) U4.17(EP) U5.8(GND1) U5.9(GND2) U5.14(~{2OE}) U5.15(~{1OE}) U5.17(PAD) U7.A1(VSS) U7.A31(VSS) U7.AA13(VSS) U7.AA14(VSS) U7.AA15(VSS) U7.AA16(VSS) U7.AA17(VSS) U7.AA18(VSS) U7.AA27(VSS) U7.AC7(VSSA_CSI2) U7.AC25(VSS) U7.AD3(VSS) U7.AD4(VSS) U7.AD5(VSS) U7.AD6(VSS) U7.AD7(VSS) U7.AD24(VSS) U7.AD25(VSS) U7.AE5(VSS) U7.AE6(VSS) U7.AE7(VSS) U7.AE8(VSS) U7.AE9(VSS) U7.AE12(VSS) U7.AE19(VSS) U7.AE20(VSS) U7.AE23(VSS) U7.AE24(VSS) U7.AE25(VSS) U7.AE26(VSS) U7.AE27(VSS) U7.AE28(VSS) U7.AF7(VSS) U7.AF12(VSS) U7.AF20(VSS) U7.AF24(VSS) U7.AF25(VSS) U7.AG7(VSS) U7.AG11(VSS) U7.AG19(VSS) U7.AG24(VSS) U7.AG25(VSS) U7.AH7(VSS) U7.AH12(VSS) U7.AH20(VSS) U7.AL1(VSS) U7.AL31(VSS) U7.C8(VSSA_VDAC) U7.D8(VSS) U7.D20(VSSA_USB) U7.D25(VSS) U7.E7(VSS) U7.E8(VSS) U7.E21(VSS) U7.E25(VSS) U7.F7(VSS) U7.F8(VSS) U7.F20(VSS) U7.F25(VSS) U7.G4(VSS) U7.G5(VSS) U7.G6(VSS) U7.G7(VSS) U7.G8(VSS) U7.G9(VSSA_HDMI) U7.G20(VSS) U7.G23(VSS) U7.G24(VSS) U7.G25(VSS) U7.G26(VSS) U7.G27(VSS) U7.H7(VSS) U7.H8(VSSA_HDMI) U7.H26(VSS) U7.J7(VSS) U7.L16(VSS) U7.M16(VSS) U7.N13(VSS) U7.N14(VSS) U7.N16(VSS) U7.N17(VSS) U7.N19(VSSA_USB) U7.N20(VSSA_USB) U7.P11(VSS) U7.P12(VSS) U7.P14(VSS) U7.P18(VSS) U7.R11(VSS) U7.R12(VSS) U7.R14(VSS) U7.R18(VSS) U7.R20(VSS) U7.R21(VSS) U7.T11(VSS) U7.T12(VSS) U7.T14(VSS) U7.T15(VSS) U7.T16(VSS) U7.T19(VSS) U7.T20(VSS) U7.T21(VSS) U7.U14(VSS) U7.U18(VSS) U7.U23(VSS) U7.V14(VSSA_CSI2) U7.V18(VSS) U7.W16(VSS) U7.W17(VSS) U7.Y16(VSS) U7.Y17(VSS) U7.Y25(VSS) U7.Y26(VSS) U7.Y28(VSS) U12.8(GND1) U12.9(GND2) U12.14(~{2OE}) U12.15(~{1OE}) U12.17(PAD) ; also on sheet 9 10 11 16 17 18 19 20 21
VCC_3V3: C15.1 C20.1 C23.1 C35.1 C40.1 C45.1 C69.1 C83.1 C91.1 C100.1 C101.1 C102.1 C103.1 C114.1 C176.1 C177.1 C178.1 MOD1.46(VBAT_IN) MOD1.47(VBAT_IN) R10.1 R57.1 R62.1 R91.1 R118.2 U2.1(VCCA) U3.19(VCCB) U4.16(VCC) U5.1(VCCA) U7.D16(DVDD) U7.E17(DVDD) U7.F16(DVDD) U7.L5(DVDD) U7.M4(DVDD) U7.M6(DVDD) U7.M7(DVDD) U7.N10(DVDD) U7.N11(DVDD) U7.R5(DVDD_GPMC) U7.R7(DVDD_GPMC) U7.T4(DVDD_GPMC) U7.T6(DVDD_GPMC) U7.T7(DVDD_GPMC) U7.T25(DVDD_SD) U7.T26(DVDD) U7.T28(DVDD) U7.U25(DVDD_SD) U7.U27(DVDD) U7.W5(DVDD_RGMII) U7.W7(DVDD_RGMII) U7.Y4(DVDD_RGMII) U7.Y6(DVDD_RGMII) U7.Y7(DVDD_RGMII) U12.1(VCCA) ; also on sheet 9 10 16 17 18 19 21 22
VCC_CAM: C118.1 R117.1 R118.1 U7.D12(DVDD_C) U7.E13(DVDD_C) U7.F12(DVDD_C) U7.G12(DVDD_C) U7.G13(DVDD_C) ; also on sheet 21
VDD_DDR: C121.2 C122.1 C127.1 C128.2 C135.1 C141.1 C182.1 U7.AB14(DVDD_DDR[0]) U7.AB15(DVDD_DDR[0]) U7.AB17(DVDD_DDR[0]) U7.AB18(DVDD_DDR[0]) U7.AC15(DVDD_DDR[0]) U7.AC17(DVDD_DDR[0]) U7.AC18(DVDD_DDR[0]) U7.AE15(DVDD_DDR[0]) U7.AE16(DVDD_DDR[0]) U7.AF16(DVDD_DDR[0]) U7.AG15(DVDD_DDR[0]) U7.AH16(DVDD_DDR[0]) ; also on sheet 11 18
CLK32OUT_PMIC: R36.1 ; also on sheet 17
CORE_CVDD: C87.1 C88.1 C89.1 C124.1 C125.1 C126.1 C129.1 C131.1 C138.1 C140.1 C153.1 U7.P15(CVDD) U7.P17(CVDD) U7.R15(CVDD) U7.R17(CVDD) U7.T13(CVDD) U7.T17(CVDD) U7.T18(CVDD) U7.U11(CVDD) U7.U12(CVDD) U7.U15(CVDD) U7.U17(CVDD) U7.V11(CVDD) U7.V12(CVDD) U7.V15(CVDD) U7.V17(CVDD) U7.W13(CVDD) U7.W14(CVDD) U7.W19(CVDD) U7.W20(CVDD) U7.Y13(CVDD) U7.Y14(CVDD) U7.Y19(CVDD) U7.Y20(CVDD) ; also on sheet 16
CVDD_ARM: C113.1 C120.1 C150.2 C151.1 U7.K17(CVDD_ARM) U7.L17(CVDD_ARM) U7.L18(CVDD_ARM) U7.M13(CVDD_ARM) U7.M14(CVDD_ARM) U7.M17(CVDD_ARM) ; also on sheet 16
CVDD_HDVICP: C39.2 C41.1 C158.1 C168.1 U7.U20(CVDD_HDVICP) U7.U21(CVDD_HDVICP) U7.V20(CVDD_HDVICP) U7.V21(CVDD_HDVICP) U7.W22(CVDD_HDVICP) ; also on sheet 16
DM388_BT_EN: U12.4(1A1) ; also on sheet 10
DM388_CAM_FLD: U4.2(1B1) ; also on sheet 21
DM388_CAM_FLD_UT_CTSn: U4.4(1A) ; also on sheet 20
DM388_CAM_PCLK: R142.2 U4.5(2B1) ; also on sheet 21
DM388_CAM_PCLK_UT_RTSn: R142.1 U4.7(2A) ; also on sheet 20
DM388_McASP0_ACLKX: R52.1 ; also on sheet 22
DM388_McASP0_AFSX: R41.1 ; also on sheet 22
DM388_McASP0_AXR0: R38.1 ; also on sheet 22
DM388_McASP0_AXR1: R90.1 ; also on sheet 22
DM388_MMC0_CLK: U3.20(B1) ; also on sheet 22
DM388_MMC0_CMD: U3.18(B2) ; also on sheet 22
DM388_MMC0_DAT0: U3.17(B3) ; also on sheet 22
DM388_MMC0_DAT1: U3.16(B4) ; also on sheet 22
DM388_MMC0_DAT2: U3.15(B5) ; also on sheet 22
DM388_MMC0_DAT3: U3.14(B6) ; also on sheet 22
DM388_MUX_SEL: R53.1 U4.1(S) ; also on sheet 10
DM388_UART2_CTSn: U2.7(2A2) U4.3(1B2)
DM388_UART2_RTSn: U2.5(1A2) U4.6(2B2)
DM388_UART2_RXD: U2.6(2A1) ; also on sheet 22
DM388_UART2_TXD: U2.4(1A1) ; also on sheet 22
DM388_WLAN_CLKOUT: R36.2 R37.2 U5.7(2A2)
DM388_WLAN_CLKOUT1: R37.1 ; also on sheet 10
DM388_WLAN_EN: U12.5(1A2) ; also on sheet 10
DM388_WLAN_IRQ: U12.7(2A2) ; also on sheet 10
PLL_1V8: C119.1 C139.2 C149.2 C152.1 C160.2 C171.1 U7.AA19(VDDA_DDRPLL_1P8) U7.L13(VDDA_VIDPLL_1P8) U7.L19(VDDA_ARMPLL_1P8) U7.T23(VDDA_HDVICPPLL_1P8) U7.V9(VDDA_AUDIOPLL_1P8) U7.W11(VDDA_L3L4_1P8) ; also on sheet 16
RF_ANT1: MOD1.32(RF_ANT1) R2.1 R4.1
RF_ANT2: MOD1.18(RF_ANT2) R3.1 R5.1
TPS_HDMI_CSI_1V8: C110.2 C123.1 U7.K14(VDDA_HDMI_1P8) U7.W10(VDDA_CSI2_1P8) ; also on sheet 16
TPS_USB_1V8: C136.2 C148.1 U7.J17(VDDA_USB1_1P8) U7.K19(VDDA_USB0_1P8) ; also on sheet 16
TPS_USB_3V3: C167.2 C172.1 U7.M19(VDDA_USB_3P3) U7.M20(VDDA_USB_3P3) ; also on sheet 16
TPS_VDDA_1V8: C5.1 C24.1 C36.1 C44.1 C68.1 C115.1 C116.1 C117.1 C156.1 C157.1 C159.1 MOD1.38(VIO) R14.1 R86.1 R117.2 U2.16(VCCB) U3.2(VCCA) U5.16(VCCB) U7.M25(VDDA_1P8) U7.M26(VDDA_PCIE_1P8) U7.M28(RSV54) U7.N22(VDDA_1P8) U7.N25(VDDA_1P8) U7.N27(RSV55) U7.P20(VDDS_OSC1_1P8) U7.P21(VDDS_OSC0_1P8) U7.P23(VDDA_1P8) U7.R9(VDDA_1P8) U7.T9(VDDA_1P8) U7.T10(VDDA_1P8) U12.16(VCCB) ; also on sheet 16 21
TPS_VHD_1V1: C130.1 U7.K16(VDDA_HDDAC_1P1) ; also on sheet 16
VDAC_1V8: C133.2 C134.2 U7.J14(VDDA_VDAC_1P8) U7.L14(VDDA_HDDAC_1P8) U7.L15(VDDA_HDDACREF_1P8) ; also on sheet 16
WL_DM388_BT_EN: MOD1.41(BT_EN) U12.13(1B1)
WL_DM388_McASP0_ACLKX: R13.1 R54.2
WL_DM388_McASP0_AFSX: MOD1.58(BT_AUD_FSYNC) R47.2
WL_DM388_McASP0_AXR0: MOD1.56(BT_AUD_IN) R39.2
WL_DM388_McASP0_AXR1: MOD1.57(BT_AUD_OUT) R87.2
WL_DM388_MMC0_CLK: R89.1 U3.1(A1)
WL_DM388_MMC0_CMD: R93.1 U3.3(A2)
WL_DM388_MMC0_DAT0: RA5.5 U3.4(A3)
WL_DM388_MMC0_DAT1: RA5.6 U3.5(A4)
WL_DM388_MMC0_DAT2: RA5.7 U3.6(A5)
WL_DM388_MMC0_DAT3: RA5.8 U3.7(A6)
WL_DM388_UART2_CTSn: MOD1.50(BT_HCI_RTS) U2.10(2B2)
WL_DM388_UART2_RTSn: MOD1.51(BT_HCI_CTS) U2.12(1B2)
WL_DM388_UART2_RXD: MOD1.52(BT_HCI_TX) U2.11(2B1)
WL_DM388_UART2_TXD: MOD1.53(BT_HCI_RX) U2.13(1B1)
WL_DM388_WLAN_CLKOUT: MOD1.36(EXT_32K) U5.10(2B2)
WL_DM388_WLAN_EN: MOD1.40(WLAN_EN) U12.12(1B2)
WL_DM388_WLAN_IRQ: MOD1.14(WLAN_IRQ) R86.2 U12.10(2B2)
N11838777: C111.2 U7.AB10(LDOCAP_RAM2)
N11838793: C179.2 U7.Y24(LDOCAP_HDVICPRAM)
N11838802: C99.2 U7.U9(LDOCAP_RAM0)
N11838814: C175.2 U7.T22(LDOCAP_RAM1)
N11846918: C161.2 U7.K20(LDOCAP_ARMRAM)
N12969077: C174.2 U7.M24(LDOCAP_SERDESCLK)
N14086942: R14.2 U3.10(OE)
N14387261: R10.2 U2.2(1DIR)
N14387269: R11.1 U2.3(2DIR)
N14434808: C155.1 U7.J19(LDOCAP_ARM)
N14434812: C180.1 U7.W23(LDOCAP_HDVICP)
N14564270: R52.2 U5.4(1A1)
N14564274: R41.2 U5.5(1A2)
N14564278: R38.2 U5.6(2A1)
N14564302: R57.2 U5.3(2DIR)
N14564360: R58.1 R62.2 U5.2(1DIR)
N14565290: R92.1 U12.3(2DIR)
N14565662: R91.2 U12.2(1DIR)
N14572177: MOD1.42(WL_UART_DBG) TP6.1(TP)
N14572181: MOD1.43(BT_UART_DBG) TP5.1(TP)
N14575481: A1.1(FEED_A1) C2.2 L3.1
N14575485: A2.1(FEED_A1) C1.2 L2.1
N14575533: C2.1 R1.2 R4.2
N14575591: C1.1 L1.1 R5.2
N15013442: J1.1(FEED) R2.2
N15014410: J2.1(FEED) R3.2
N15110091: R54.1 U5.13(1B1)
N15110100: R47.1 U5.12(1B2)
N15110106: R39.1 U5.11(2B1)
N15110404: R87.1 U12.11(2B1)
N15110444: R90.2 U12.6(2A1)
N15124704: MOD1.6(WL_SDIO_CMD) R93.2
N15124708: MOD1.8(WL_SDIO_CLK) R89.2
N15124784: MOD1.10(WL_SDIO_D0) RA5.4
N15124788: MOD1.11(WL_SDIO_D1) RA5.3
N15124799: MOD1.13(WL_SDIO_D3) RA5.1
N15124807: MOD1.12(WL_SDIO_D2) RA5.2
N15124875: MOD1.60(BT_AUD_CLK) R13.2

Not connected (* = marked no-connect by the designer): A1 2(FEED_A2)*; A2 2(FEED_A2)*; MOD1 2(GPIO11)* 3(GPIO9)* 4(GPIO10)* 5(GPIO12)* 21(RESERVED1)* 22(RESERVED2)* 25(GPIO4)* 26(GPIO2)* 27(GPIO1)* 62(RESERVED3)*; U3 8(A7)* 9(A8)* 12(B8)* 13(B7)*; U4 10(3B2)* 11(3B1)* 13(4B2)* 14(4B1)*; U7 G16(RSV5)* G17(RSV4)*

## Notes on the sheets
sheet 12
- WLAN TRANSLATORS
- USE TRIPAD HERE
- DIRECTION CONTROL
- DIRECTION CONTROL
- 1A
- 1B
- 1B
- 1A
- 2A
- 2B
- 2A
- 2B
- DIRECTION CONTROL
- DIRECTION CONTROL
- 1A
- 1B
- 2A
- 2B
- B
- A
- UART & CAM MUXER
- DEFAULT SELECTION : CAMERA
sheet 13
- WLAN + BT MODULE
sheet 14
- DM388 POWER
- USE TRIPAD HERE
sheet 15
- DM388 VSS
